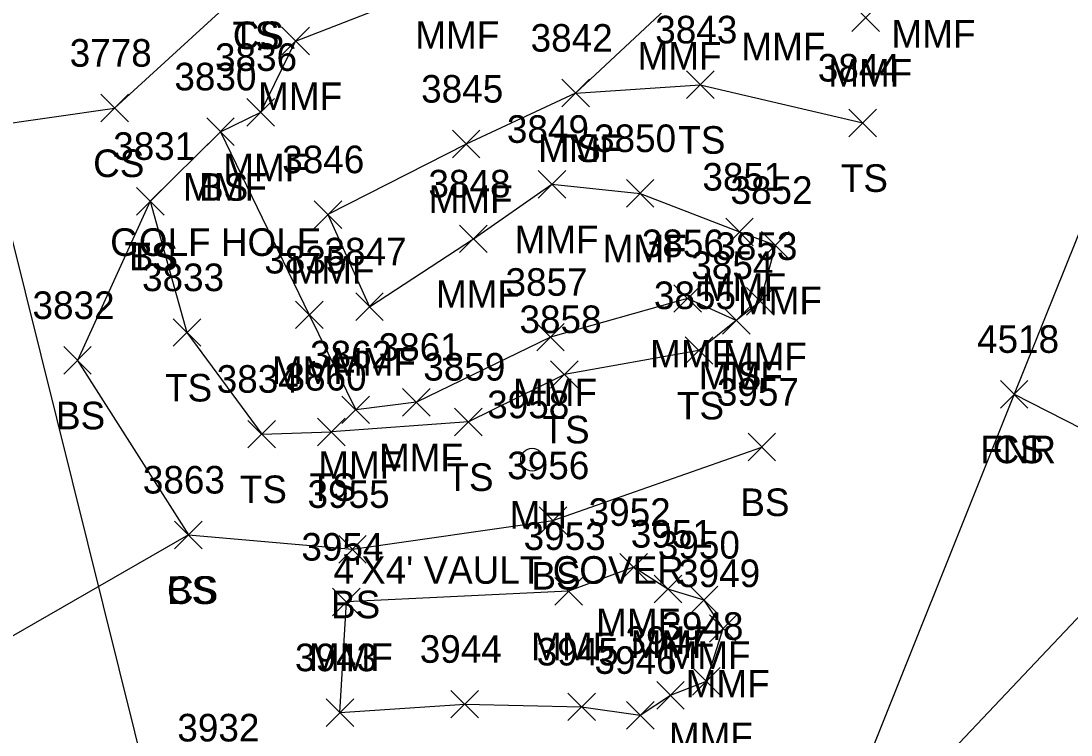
# Model space of a CAD drawing. Extents: x 49137 to 50946, y 9590 to 10709.
# Drawn here: x 50054.1 to 50130.2, y 10323.2 to 10375 of the extents above; entities that cross this region are included whole.
import ezdxf

# ---------------------------------------------------------------- set-up
doc = ezdxf.new("R2010")
doc.units = 0
for name, color, linetype in [('DCP', 7, 'Continuous'), ('L_A', 7, 'Continuous'), ('L_C', 7, 'Continuous'), ('L_I', 7, 'Continuous'), ('L_TIC', 7, 'Continuous'), ('LDEFAULT', 7, 'Continuous'), ('LELB', 7, 'Continuous'), ('LFNC', 7, 'Continuous'), ('U_A', 7, 'Continuous'), ('U_C', 7, 'Continuous'), ('U_I', 7, 'Continuous'), ('UUMH', 7, 'Continuous')]:
    doc.layers.add(name, color=color, linetype=linetype)

msp = doc.modelspace()

# ---------------------------------------------------------------- linework, layer by layer
at = {"layer": 'DCP'}
msp.add_lwpolyline([(50149.417, 9973.365), (49988.848, 10619.092)], dxfattribs=at)
at = {"layer": 'L_TIC'}
for points in [[(50114.351, 10374.251), (50116.351, 10376.251)], [(50116.351, 10374.251), (50114.351, 10376.251)], [(50073.021, 10372.547), (50075.021, 10374.547)], [(50075.021, 10372.547), (50073.021, 10374.547)], [(50102.353, 10369.38), (50104.353, 10371.38)], [(50104.353, 10369.38), (50102.353, 10371.38)], [(50093.319, 10368.779), (50095.319, 10370.779)], [(50095.319, 10368.779), (50093.319, 10370.779)], [(50093.319, 10368.779), (50095.319, 10370.779)], [(50095.319, 10368.779), (50093.319, 10370.779)], [(50059.907, 10367.69), (50061.907, 10369.69)], [(50061.907, 10367.69), (50059.907, 10369.69)], [(50070.497, 10367.385), (50072.497, 10369.385)], [(50072.497, 10367.385), (50070.497, 10369.385)], [(50114.134, 10366.615), (50116.134, 10368.615)], [(50116.134, 10366.615), (50114.134, 10368.615)], [(50067.582, 10365.974), (50069.582, 10367.974)], [(50069.582, 10365.974), (50067.582, 10367.974)], [(50067.582, 10365.974), (50069.582, 10367.974)], [(50069.582, 10365.974), (50067.582, 10367.974)], [(50067.582, 10365.974), (50069.582, 10367.974)], [(50069.582, 10365.974), (50067.582, 10367.974)], [(50085.385, 10365.087), (50087.385, 10367.087)], [(50087.385, 10365.087), (50085.385, 10367.087)], [(50091.608, 10362.171), (50093.608, 10364.171)], [(50093.608, 10362.171), (50091.608, 10364.171)], [(50098.002, 10361.503), (50100.002, 10363.503)], [(50100.002, 10361.503), (50098.002, 10363.503)], [(50062.493, 10360.935), (50064.493, 10362.935)], [(50064.493, 10360.935), (50062.493, 10362.935)], [(50062.493, 10360.935), (50064.493, 10362.935)], [(50064.493, 10360.935), (50062.493, 10362.935)], [(50075.367, 10359.97), (50077.367, 10361.97)], [(50077.367, 10359.97), (50075.367, 10361.97)], [(50085.909, 10358.213), (50087.909, 10360.213)], [(50087.909, 10358.213), (50085.909, 10360.213)], [(50105.202, 10358.709), (50107.202, 10360.709)], [(50107.202, 10358.709), (50105.202, 10360.709)], [(50107.802, 10357.745), (50109.802, 10359.745)], [(50109.802, 10357.745), (50107.802, 10359.745)], [(50101.437, 10353.887), (50103.437, 10355.887)], [(50103.437, 10353.887), (50101.437, 10355.887)], [(50106.709, 10353.68), (50108.709, 10355.68)], [(50108.709, 10353.68), (50106.709, 10355.68)], [(50078.378, 10353.287), (50080.378, 10355.287)], [(50080.378, 10353.287), (50078.378, 10355.287)], [(50074.018, 10352.701), (50076.018, 10354.701)], [(50076.018, 10352.701), (50074.018, 10354.701)], [(50104.964, 10352.299), (50106.964, 10354.299)], [(50106.964, 10352.299), (50104.964, 10354.299)], [(50104.964, 10352.299), (50106.964, 10354.299)], [(50106.964, 10352.299), (50104.964, 10354.299)], [(50065.151, 10351.421), (50067.151, 10353.421)], [(50067.151, 10351.421), (50065.151, 10353.421)], [(50091.501, 10351.083), (50093.501, 10353.083)], [(50093.501, 10351.083), (50091.501, 10353.083)], [(50102.255, 10350.12), (50104.255, 10352.12)], [(50104.255, 10350.12), (50102.255, 10352.12)], [(50057.213, 10349.402), (50059.213, 10351.402)], [(50059.213, 10349.402), (50057.213, 10351.402)], [(50092.51, 10348.38), (50094.51, 10350.38)], [(50094.51, 10348.38), (50092.51, 10350.38)], [(50125.111, 10346.947), (50127.111, 10348.947)], [(50127.111, 10346.947), (50125.111, 10348.947)], [(50125.111, 10346.947), (50127.111, 10348.947)], [(50127.111, 10346.947), (50125.111, 10348.947)], [(50081.783, 10346.369), (50083.783, 10348.369)], [(50083.783, 10346.369), (50081.783, 10348.369)], [(50077.379, 10345.819), (50079.379, 10347.819)], [(50079.379, 10345.819), (50077.379, 10347.819)], [(50077.379, 10345.819), (50079.379, 10347.819)], [(50079.379, 10345.819), (50077.379, 10347.819)], [(50085.547, 10344.935), (50087.547, 10346.935)], [(50087.547, 10344.935), (50085.547, 10346.935)], [(50070.566, 10344.054), (50072.566, 10346.054)], [(50072.566, 10344.054), (50070.566, 10346.054)], [(50075.614, 10344.214), (50077.614, 10346.214)], [(50077.614, 10344.214), (50075.614, 10346.214)], [(50075.614, 10344.214), (50077.614, 10346.214)], [(50077.614, 10344.214), (50075.614, 10346.214)], [(50106.818, 10343.115), (50108.818, 10345.115)], [(50108.818, 10343.115), (50106.818, 10345.115)], [(50091.678, 10337.787), (50093.678, 10339.787)], [(50093.678, 10337.787), (50091.678, 10339.787)], [(50065.256, 10336.749), (50067.256, 10338.749)], [(50067.256, 10336.749), (50065.256, 10338.749)], [(50065.256, 10336.749), (50067.256, 10338.749)], [(50067.256, 10336.749), (50065.256, 10338.749)], [(50077.15, 10335.707), (50079.15, 10337.707)], [(50079.15, 10335.707), (50077.15, 10337.707)], [(50097.522, 10334.406), (50099.522, 10336.406)], [(50099.522, 10334.406), (50097.522, 10336.406)], [(50092.812, 10332.659), (50094.812, 10334.659)], [(50094.812, 10332.659), (50092.812, 10334.659)], [(50100.015, 10332.828), (50102.015, 10334.828)], [(50102.015, 10332.828), (50100.015, 10334.828)], [(50076.703, 10331.887), (50078.703, 10333.887)], [(50078.703, 10331.887), (50076.703, 10333.887)], [(50076.703, 10331.887), (50078.703, 10333.887)], [(50078.703, 10331.887), (50076.703, 10333.887)], [(50102.628, 10332.03), (50104.628, 10334.03)], [(50104.628, 10332.03), (50102.628, 10334.03)], [(50104.017, 10329.967), (50106.017, 10331.967)], [(50106.017, 10329.967), (50104.017, 10331.967)], [(50102.796, 10326.142), (50104.796, 10328.142)], [(50104.796, 10326.142), (50102.796, 10328.142)], [(50100.198, 10325.121), (50102.198, 10327.121)], [(50102.198, 10325.121), (50100.198, 10327.121)], [(50085.283, 10324.478), (50087.283, 10326.478)], [(50087.283, 10324.478), (50085.283, 10326.478)], [(50093.757, 10324.285), (50095.757, 10326.285)], [(50095.757, 10324.285), (50093.757, 10326.285)], [(50076.236, 10323.868), (50078.236, 10325.868)], [(50078.236, 10323.868), (50076.236, 10325.868)], [(50076.236, 10323.868), (50078.236, 10325.868)], [(50078.236, 10323.868), (50076.236, 10325.868)], [(50098.005, 10323.676), (50100.005, 10325.676)], [(50100.005, 10323.676), (50098.005, 10325.676)]]:
    msp.add_lwpolyline(points, dxfattribs=at)
at = {"layer": 'LDEFAULT'}
for points in [[(50068.582, 10366.974), (50071.497, 10368.385), (50074.021, 10373.547), (50085.418, 10377.99), (50092.593, 10381.563), (50099.991, 10380.781), (50101.522, 10376.482), (50094.319, 10369.779), (50086.385, 10366.087), (50076.367, 10360.97), (50079.378, 10354.287), (50086.909, 10359.213), (50092.608, 10363.171), (50099.002, 10362.503), (50106.202, 10359.709), (50108.802, 10358.745), (50107.709, 10354.68), (50105.964, 10353.299), (50102.437, 10354.887), (50092.501, 10352.083), (50082.783, 10347.369), (50078.379, 10346.819)], [(50068.582, 10366.974), (50075.018, 10353.701), (50078.379, 10346.819)], [(50077.236, 10324.868), (50086.283, 10325.478), (50094.757, 10325.285), (50099.005, 10324.676), (50101.198, 10326.121), (50103.796, 10327.142), (50105.017, 10330.967), (50103.628, 10333.03), (50101.015, 10333.828), (50098.522, 10335.406), (50093.812, 10333.659), (50077.703, 10332.887)], [(50077.236, 10324.868), (50077.703, 10332.887)]]:
    msp.add_lwpolyline(points, dxfattribs=at)
at = {"layer": 'LELB'}
for points in [[(50019.697, 10350.956), (50018.697, 10360.413), (50027.458, 10369.871), (50043.148, 10372.476), (50051.46, 10367.333), (50060.907, 10368.69), (50071.028, 10377.965)], [(50094.319, 10369.779), (50103.353, 10370.38), (50115.134, 10367.615)], [(50068.582, 10366.974), (50063.493, 10361.935), (50058.213, 10350.402), (50066.256, 10337.749), (50078.15, 10336.707), (50092.678, 10338.787), (50107.818, 10344.115)], [(50063.493, 10361.935), (50066.151, 10352.421), (50071.566, 10345.054), (50076.614, 10345.214)], [(50105.964, 10353.299), (50103.255, 10351.12), (50093.51, 10349.38), (50086.547, 10345.935), (50076.614, 10345.214)], [(50126.111, 10347.947), (50139.577, 10341.078), (50151.209, 10326.927), (50148.29, 10305.426)], [(50139.577, 10341.078), (50116.581, 10316.815), (50105.504, 10295.618)], [(50066.256, 10337.749), (50045.996, 10326.102), (50031.571, 10318.205), (50024.186, 10311.328), (50008.365, 10283.785), (50010.84, 10269.9), (50019.682, 10261.76), (50041.865, 10254.082), (50068.201, 10243.093)]]:
    msp.add_lwpolyline(points, dxfattribs=at)
at = {"layer": 'LFNC'}
msp.add_lwpolyline([(50137.912, 10377.263), (50126.111, 10347.947), (50114.055, 10317.815), (50105.504, 10295.618), (50093.252, 10266.236)], dxfattribs=at)
at = {"layer": 'UUMH'}
for p, q in [((50091.172, 10343.208), (50091.172, 10343.208)), ((50092.005, 10343.208), (50092.005, 10343.208))]:
    msp.add_line(p, q, dxfattribs=at)
msp.add_circle((50091.172, 10343.208), 0.833, dxfattribs=at)

# ---------------------------------------------------------------- texts
at = {"layer": 'L_A'}
for s, p in [('TS', (50069.438, 10372.965)), ('CS', (50069.469, 10372.965)), ('MMF', (50082.701, 10372.99)), ('MMF', (50117.213, 10373.073)), ('MMF', (50106.337, 10372.148)), ('MMF', (50098.806, 10371.482)), ('MMF', (50112.634, 10370.251)), ('MMF', (50071.305, 10368.547)), ('TS', (50101.762, 10365.38)), ('MMF', (50091.602, 10364.779)), ('TS', (50092.728, 10364.779)), ('CS', (50059.348, 10363.69)), ('MMF', (50068.78, 10363.385)), ('MMF', (50065.865, 10361.974)), ('MMF', (50065.865, 10361.974)), ('BS', (50067.023, 10361.974)), ('TS', (50113.544, 10362.615)), ('MMF', (50083.669, 10361.087)), ('MMF', (50089.891, 10358.171)), ('MMF', (50096.286, 10357.503)), ('TS', (50061.903, 10356.935)), ('BS', (50061.934, 10356.935)), ('MMF', (50073.651, 10355.97)), ('MMF', (50103.485, 10354.709)), ('MMF', (50084.193, 10354.213)), ('MMF', (50106.086, 10353.745)), ('MMF', (50099.721, 10349.887)), ('MMF', (50076.661, 10349.287)), ('MMF', (50104.992, 10349.68)), ('MMF', (50072.302, 10348.701)), ('MMF', (50103.248, 10348.299)), ('TS', (50104.374, 10348.299)), ('TS', (50064.56, 10347.421)), ('MMF', (50089.784, 10347.083)), ('TS', (50101.664, 10346.12)), ('BS', (50056.654, 10345.402)), ('TS', (50091.92, 10344.38)), ('FNR', (50123.647, 10342.947)), ('CS', (50124.552, 10342.947)), ('MMF', (50080.067, 10342.369)), ('MMF', (50075.663, 10341.819)), ('MMF', (50075.663, 10341.819)), ('TS', (50084.956, 10340.935)), ('TS', (50069.976, 10340.054)), ('TS', (50075.024, 10340.214)), ('TS', (50075.024, 10340.214)), ('BS', (50106.259, 10339.115)), ('BS', (50091.119, 10333.787)), ('CS', (50064.697, 10332.749)), ('BS', (50064.697, 10332.749)), ('BS', (50076.591, 10331.707)), ('MMF', (50095.806, 10330.406)), ('MMF', (50091.095, 10328.659)), ('MMF', (50098.298, 10328.828)), ('MMF', (50074.987, 10327.887)), ('MMF', (50074.987, 10327.887)), ('MMF', (50100.911, 10328.03)), ('MMF', (50102.301, 10325.967)), ('MMF', (50101.079, 10322.142))]:
    msp.add_text(s, height=2, dxfattribs=at).set_placement(p)
at = {"layer": 'L_C'}
msp.add_text('GOLF HOLE', height=2, dxfattribs=at).set_placement((50060.582, 10357.974))
msp.add_text('GOLF HOLE', height=2, dxfattribs=at).set_placement((50060.582, 10357.974))
at = {"layer": 'L_I'}
for s, p in [('3843', (50100.093, 10373.38)), ('3842', (50091.059, 10372.779)), ('3842', (50091.059, 10372.779)), ('3778', (50057.647, 10371.69)), ('3836', (50068.182, 10371.385)), ('3844', (50111.875, 10370.615)), ('3830', (50065.235, 10369.974)), ('3830', (50065.235, 10369.974)), ('3830', (50065.235, 10369.974)), ('3845', (50083.125, 10369.087)), ('3849', (50089.34, 10366.171)), ('3850', (50095.656, 10365.503)), ('3831', (50060.8, 10364.935)), ('3831', (50060.8, 10364.935)), ('3846', (50073.052, 10363.97)), ('3851', (50103.509, 10362.709)), ('3848', (50083.649, 10362.213)), ('3852', (50105.542, 10361.745)), ('3856', (50099.122, 10357.887)), ('3853', (50104.449, 10357.68)), ('3835', (50071.758, 10356.701)), ('3847', (50076.118, 10357.287)), ('3854', (50102.705, 10356.299)), ('3854', (50102.705, 10356.299)), ('3833', (50062.891, 10355.421)), ('3857', (50089.241, 10355.083)), ('3855', (50099.995, 10354.12)), ('3832', (50054.953, 10353.402)), ('3858', (50090.251, 10352.38)), ('4518', (50123.419, 10350.947)), ('4518', (50123.419, 10350.947)), ('3862', (50075.072, 10349.819)), ('3862', (50075.072, 10349.819)), ('3861', (50080.043, 10350.369)), ('3859', (50083.279, 10348.935)), ('3834', (50068.306, 10348.054)), ('3860', (50073.221, 10348.214)), ('3860', (50073.221, 10348.214)), ('3957', (50104.559, 10347.115)), ('3956', (50089.363, 10341.787)), ('3863', (50062.949, 10340.749)), ('3863', (50062.949, 10340.749)), ('3955', (50074.89, 10339.707)), ('3952', (50095.263, 10338.406)), ('3951', (50098.322, 10336.828)), ('3953', (50090.552, 10336.659)), ('3954', (50074.444, 10335.887)), ('3954', (50074.444, 10335.887)), ('3950', (50100.282, 10336.03)), ('3949', (50101.75, 10333.967)), ('3948', (50100.536, 10330.142)), ('3944', (50083.023, 10328.478)), ('3947', (50097.938, 10329.121)), ('3943', (50073.976, 10327.868)), ('3943', (50073.976, 10327.868)), ('3945', (50091.497, 10328.285)), ('3946', (50095.69, 10327.676)), ('3932', (50065.451, 10322.776)), ('3932', (50065.451, 10322.776))]:
    msp.add_text(s, height=2, dxfattribs=at).set_placement(p)
at = {"layer": 'U_A'}
msp.add_text('MH', height=2, dxfattribs=at).set_placement((50089.534, 10338.208))
at = {"layer": 'U_C'}
msp.add_text("4'X4' VAULT COVER", height=2, dxfattribs=at).set_placement((50076.77, 10334.208))
at = {"layer": 'U_I'}
msp.add_text('3958', height=2, dxfattribs=at).set_placement((50087.912, 10346.208))

doc.saveas('drawing.dxf')
